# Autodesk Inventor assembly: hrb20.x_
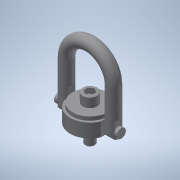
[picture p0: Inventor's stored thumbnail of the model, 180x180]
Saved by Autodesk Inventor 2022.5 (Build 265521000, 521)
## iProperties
Part Number: hrb20.x_
Material: 一般
Document SubType Name: Assembly
Designer: ImaoCorp
Sending System: SOLIDWORKS 2017-2017317
MC: AMD64
MC_MODEL: Intel64 Family 6 Model 60 Stepping 3, GenuineIntel
OS: Windows_NT
FRU: Parasolid Version 29.0, build 201,  4-17-2017
FORMAT: text
GUISE: transmit
KEY: hrb20
FILE: hrb20.x_t
DATE: Mon Jul 01 17:38:55 2019
Author: ImaoCorp
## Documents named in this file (3)
- X:\14_SW2022-Inv2022\00_全2023-1023新製品(TCC)まで\h\hrb20\HRB20.iam
- X:\14_SW2022-Inv2022\00_全2023-1023新製品(TCC)まで\h\hrb20\hrb20_01.ipt
- X:\14_SW2022-Inv2022\00_全2023-1023新製品(TCC)まで\h\hrb20\hrb20_02.ipt
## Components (2 placed, 2 different names)
1. hrb20_01
2. hrb20_02
